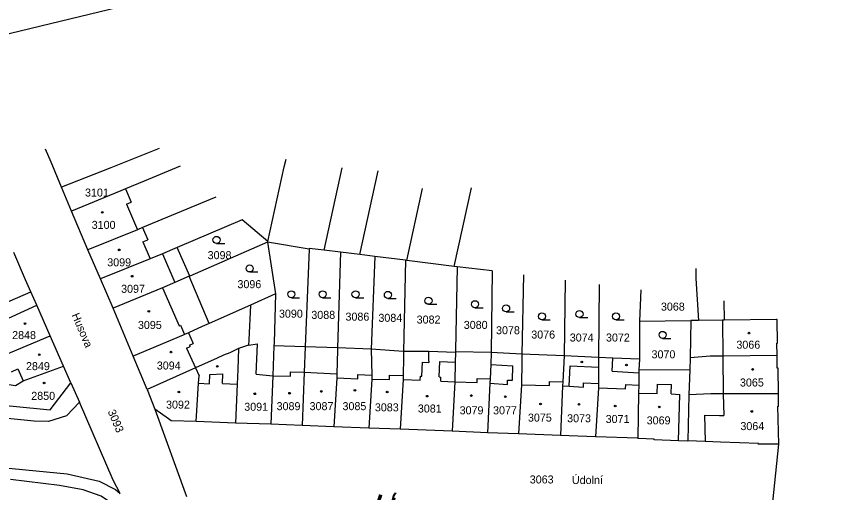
# Model space of a CAD drawing. Extents: x -738085 to -734306, y -1122197 to -1119753.
# Drawn here: x -734745.8 to -734573.1, y -1120143.5 to -1120042.4 of the extents above; entities that cross this region are included whole.
import ezdxf

# ---------------------------------------------------------------- set-up
doc = ezdxf.new("R2010")
doc.units = 0
for name, color, linetype in [('Hranice parcel', 7, 'Continuous'), ('Parcelní čísla', 7, 'Continuous'), ('Pop  PČ popisy', 7, 'Continuous'), ('Vnitřní kresba', 7, 'Continuous'), ('Vrstva 1', 7, 'Continuous'), ('Vrstva 7', 7, 'Continuous'), ('Značky budov', 7, 'Continuous'), ('Značky kultur', 7, 'Continuous')]:
    doc.layers.add(name, color=color, linetype=linetype)

msp = doc.modelspace()

# ---------------------------------------------------------------- linework, layer by layer
at = {"layer": 'Hranice parcel'}
for p, q in [((-734680.42, -1120092.08), (-734676.55, -1120074.57)), ((-734672.81, -1120093.01), (-734668.96, -1120075.25)), ((-734734, -1120083.8), (-734736.13, -1120078.7)), ((-734662.86, -1120094.24), (-734659.5, -1120078.96)), ((-734652.78, -1120095.52), (-734649.12, -1120078.87)), ((-734730.53, -1120091.97), (-734734, -1120083.8)), ((-734697.79, -1120085.62), (-734711.61, -1120091.5)), ((-734692.37, -1120090.23), (-734697.79, -1120085.62)), ((-734692.41, -1120090.4), (-734708.91, -1120097.56)), ((-734692.41, -1120090.4), (-734692.37, -1120090.23)), ((-734683.6, -1120091.87), (-734692.41, -1120090.4)), ((-734692.41, -1120090.4), (-734690.71, -1120101.34)), ((-734727.88, -1120098.19), (-734730.53, -1120091.97)), ((-734708.91, -1120097.56), (-734711.61, -1120091.5)), ((-734683.6, -1120091.87), (-734684.42, -1120112.56)), ((-734676.96, -1120092.51), (-734680.42, -1120092.08)), ((-734676.96, -1120092.51), (-734677.59, -1120112.79)), ((-734672.81, -1120093.01), (-734676.96, -1120092.51)), ((-734669.67, -1120093.4), (-734672.81, -1120093.01)), ((-734669.67, -1120093.4), (-734670.4, -1120113.05)), ((-734663.11, -1120094.23), (-734669.67, -1120093.4)), ((-734663.11, -1120094.23), (-734663.52, -1120113.54)), ((-734662.86, -1120094.24), (-734663.11, -1120094.23)), ((-734652.78, -1120095.52), (-734662.86, -1120094.24)), ((-734652.19, -1120095.59), (-734652.78, -1120095.52)), ((-734644.76, -1120096.47), (-734652.19, -1120095.59)), ((-734708.91, -1120097.56), (-734709.02, -1120097.6)), ((-734704.79, -1120107.63), (-734709.02, -1120097.6)), ((-734644.76, -1120096.47), (-734644.93, -1120113.82)), ((-734638.11, -1120097.31), (-734638.44, -1120114.16)), ((-734725.22, -1120104.37), (-734727.88, -1120098.19)), ((-734629.26, -1120098.44), (-734629.48, -1120114.51)), ((-734621.99, -1120099.36), (-734622.13, -1120114.88)), ((-734690.71, -1120101.34), (-734696.03, -1120103.72)), ((-734613.2, -1120100.48), (-734613.47, -1120107.14)), ((-734738.55, -1120110.28), (-734741.41, -1120103.73)), ((-734720.97, -1120114.53), (-734725.22, -1120104.37)), ((-734696.03, -1120103.72), (-734704.79, -1120107.63)), ((-734613.47, -1120107.14), (-734602.57, -1120106.99)), ((-734613.47, -1120107.14), (-734613.47, -1120115.18)), ((-734602.57, -1120106.99), (-734602.67, -1120114.92)), ((-734600.93, -1120106.97), (-734602.57, -1120106.99)), ((-734735.7, -1120116.71), (-734738.55, -1120110.28)), ((-734684.42, -1120112.56), (-734691.06, -1120112.35)), ((-734677.59, -1120112.79), (-734684.42, -1120112.56)), ((-734670.4, -1120113.05), (-734677.59, -1120112.79)), ((-734663.52, -1120113.54), (-734670.4, -1120113.05)), ((-734717.99, -1120121.62), (-734720.97, -1120114.53)), ((-734644.93, -1120113.82), (-734652.54, -1120113.64)), ((-734652.54, -1120113.64), (-734652.54, -1120113.79)), ((-734638.44, -1120114.16), (-734644.93, -1120113.82)), ((-734629.48, -1120114.51), (-734638.44, -1120114.16)), ((-734622.13, -1120114.88), (-734629.48, -1120114.51)), ((-734613.47, -1120115.18), (-734613.62, -1120117.52)), ((-734602.67, -1120114.92), (-734602.78, -1120117.44)), ((-734734.16, -1120120.2), (-734735.7, -1120116.71)), ((-734602.78, -1120117.44), (-734613.62, -1120117.52)), ((-734602.78, -1120117.44), (-734603.01, -1120122.78)), ((-734734.16, -1120120.2), (-734732.31, -1120124.29)), ((-734717.99, -1120121.62), (-734716.35, -1120125.79)), ((-734603.01, -1120122.78), (-734603.19, -1120132.52)), ((-734716.35, -1120125.79), (-734709.6, -1120144.34)), ((-734691.73, -1120129.02), (-734699.23, -1120128.75)), ((-734685.05, -1120129.27), (-734691.73, -1120129.02)), ((-734678.37, -1120129.56), (-734685.05, -1120129.27)), ((-734670.88, -1120129.86), (-734678.37, -1120129.56)), ((-734664.23, -1120130.05), (-734670.88, -1120129.86)), ((-734653.23, -1120130.5), (-734664.23, -1120130.05)), ((-734645.73, -1120130.82), (-734653.23, -1120130.5)), ((-734639.14, -1120131.04), (-734645.73, -1120130.82)), ((-734630.24, -1120131.41), (-734639.14, -1120131.04)), ((-734622.77, -1120131.68), (-734630.24, -1120131.41)), ((-734613.81, -1120131.98), (-734622.77, -1120131.68)), ((-734585.56, -1120149.21), (-734583.88, -1120133.2))]:
    msp.add_line(p, q, dxfattribs=at)
for points in [[(-734736.13, -1120078.7), (-734738.38, -1120073.38), (-734739.58, -1120070.62)], [(-734715.39, -1120070.51), (-734725.68, -1120074.58), (-734736.13, -1120078.7)], [(-734692.37, -1120090.23), (-734688.87, -1120074.42), (-734688.46, -1120072.79)], [(-734710.98, -1120074.27), (-734718.6, -1120077.41), (-734722.56, -1120079.04), (-734723.58, -1120079.46), (-734734, -1120083.8)], [(-734703.41, -1120080.84), (-734718.98, -1120087.3), (-734720.01, -1120087.73), (-734730.53, -1120091.97)], [(-734741.41, -1120103.73), (-734742.65, -1120100.94), (-734743.81, -1120098.34), (-734746.27, -1120092.6)], [(-734711.61, -1120091.5), (-734714.71, -1120092.82), (-734717.33, -1120093.93), (-734727.88, -1120098.19)], [(-734680.42, -1120092.08), (-734683.59, -1120091.7), (-734683.6, -1120091.87)], [(-734652.19, -1120095.59), (-734652.53, -1120113.36), (-734652.54, -1120113.64)], [(-734601.52, -1120095.93), (-734601.53, -1120098.07), (-734600.93, -1120106.97)], [(-734709.02, -1120097.6), (-734712.13, -1120098.95), (-734714.69, -1120100.06), (-734725.22, -1120104.37)], [(-734690.71, -1120101.34), (-734691.04, -1120111.73), (-734691.06, -1120112.35)], [(-734732.31, -1120124.29), (-734735.07, -1120127.22), (-734738.9, -1120128.4), (-734741.96, -1120128.37), (-734978.31, -1120104.89), (-734995.05, -1120103.5), (-735001.08, -1120103.64), (-735005.96, -1120104.65), (-735026.65, -1120111.99), (-735048.37, -1120119.26), (-735164.14, -1120157.32), (-735176.88, -1120160.91), (-735184.81, -1120162.43), (-735185.96, -1120162.53), (-735190.85, -1120162.98), (-735196.87, -1120162.75), (-735201.79, -1120161.48), (-735203.71, -1120160.98), (-735206.41, -1120159.5), (-735208.64, -1120157.56), (-735225.14, -1120141.26)], [(-734753.79, -1120107.64), (-734751.4, -1120108.03), (-734751.46, -1120107.88), (-734749.29, -1120107.32), (-734741.41, -1120103.73)], [(-734696.03, -1120103.72), (-734696.4, -1120111.12), (-734696.45, -1120112.2), (-734698.55, -1120112.94)], [(-734704.79, -1120107.63), (-734706.3, -1120108.3), (-734709.2, -1120109.6), (-734710.03, -1120109.96), (-734710.35, -1120110.11), (-734720.97, -1120114.53)], [(-734584.4, -1120106.77), (-734595.5, -1120106.9), (-734595.81, -1120106.9), (-734600.93, -1120106.97)], [(-734584.26, -1120114.44), (-734584.32, -1120111.82), (-734584.17, -1120111.82), (-734584.26, -1120106.77), (-734584.4, -1120106.77)], [(-735187.2, -1120177.07), (-735186.92, -1120175.94), (-735186.47, -1120174.12), (-735185.21, -1120172.48), (-735182.42, -1120171.13), (-735165.98, -1120166.38), (-735013.95, -1120116.34), (-735003.48, -1120113.01), (-735000.64, -1120112.19), (-735000, -1120112.13), (-734996.62, -1120111.83), (-734988.63, -1120112.11), (-734951.68, -1120115.51), (-734795.1, -1120131), (-734756.12, -1120134.99), (-734754.2, -1120137.32), (-734753.31, -1120137.78), (-734734.93, -1120139.52), (-734728.17, -1120141.08), (-734724.68, -1120142.84), (-734723.73, -1120143.69)], [(-734754.25, -1120116.86), (-734748.32, -1120114.37), (-734738.55, -1120110.28)], [(-734698.55, -1120112.94), (-734700.44, -1120113.83), (-734701.75, -1120114.37), (-734703.08, -1120115.02), (-734707.73, -1120117.04), (-734717.99, -1120121.62)], [(-734698.55, -1120112.94), (-734698.74, -1120117.36), (-734698.88, -1120120.5), (-734699.23, -1120128.75)], [(-734691.06, -1120112.35), (-734691.32, -1120118.72), (-734691.73, -1120129.02)], [(-734684.42, -1120112.56), (-734684.64, -1120117.95), (-734685.05, -1120129.27)], [(-734677.59, -1120112.79), (-734677.6, -1120113.26), (-734677.72, -1120118.31), (-734677.74, -1120119.17), (-734678.37, -1120129.56)], [(-734670.4, -1120113.05), (-734670.28, -1120118.59), (-734670.26, -1120119.45), (-734670.88, -1120129.86)], [(-734663.52, -1120113.54), (-734663.55, -1120114.85), (-734663.62, -1120118.67), (-734663.63, -1120119.54), (-734664.23, -1120130.05)], [(-734652.54, -1120113.79), (-734658.19, -1120113.59), (-734663.52, -1120113.54)], [(-734652.54, -1120113.79), (-734652.58, -1120115.81), (-734652.66, -1120119.99), (-734653.23, -1120130.5)], [(-734644.93, -1120113.82), (-734645.05, -1120116.35), (-734645.19, -1120119.36), (-734645.23, -1120120.26), (-734645.73, -1120130.82)], [(-734638.44, -1120114.16), (-734638.47, -1120116.66), (-734638.51, -1120119.71), (-734638.52, -1120120.65), (-734639.14, -1120131.04)], [(-734629.48, -1120114.51), (-734629.73, -1120120.02), (-734629.77, -1120120.88), (-734630.24, -1120131.41)], [(-734622.13, -1120114.88), (-734622.15, -1120116.92), (-734622.18, -1120120.36), (-734622.19, -1120121.25), (-734622.77, -1120131.68)], [(-734613.47, -1120115.18), (-734619.14, -1120114.98), (-734622.13, -1120114.88)], [(-734584.26, -1120114.44), (-734595.79, -1120114.55), (-734598.45, -1120114.58), (-734602.67, -1120114.92)], [(-734583.98, -1120122.55), (-734584.05, -1120117.09), (-734584.2, -1120117.09), (-734584.26, -1120114.44)], [(-734754.43, -1120119.69), (-734747.32, -1120120.59), (-734745.89, -1120120.77), (-734744.27, -1120119.8), (-734735.7, -1120116.71)], [(-734613.62, -1120117.52), (-734613.63, -1120118.11), (-734613.61, -1120120.72), (-734613.69, -1120122.41), (-734613.81, -1120131.98)], [(-734754.69, -1120124.4), (-734746.39, -1120125.14), (-734738.56, -1120125.97), (-734734.16, -1120120.2)], [(-734583.98, -1120122.55), (-734595.67, -1120122.56), (-734598.31, -1120122.56), (-734603.01, -1120122.78)], [(-734583.88, -1120133.2), (-734584.08, -1120125.19), (-734583.94, -1120125.19), (-734583.98, -1120122.55)], [(-734723.73, -1120143.69), (-734725.18, -1120140.86), (-734732.31, -1120124.29)], [(-734699.23, -1120128.75), (-734707.54, -1120128.46), (-734712.88, -1120128.26), (-734713.42, -1120127.87), (-734716.35, -1120125.79)], [(-734603.19, -1120132.52), (-734603.19, -1120132.58), (-734605.18, -1120132.53), (-734610.37, -1120132.29), (-734610.36, -1120132.14), (-734613.76, -1120132.06), (-734613.81, -1120131.98)], [(-734583.88, -1120133.2), (-734584.36, -1120133.25), (-734588.24, -1120133.27), (-734588.23, -1120133.07), (-734596.23, -1120132.78), (-734599.51, -1120132.66), (-734603.19, -1120132.52)], [(-734719.95, -1120151.88), (-734721.91, -1120149.18), (-734724.49, -1120146.43), (-734727.73, -1120144.25), (-734731.57, -1120142.94), (-734736.55, -1120141.99), (-734746.98, -1120140.71)]]:
    msp.add_lwpolyline(points, dxfattribs=at)
at = {"layer": 'Vnitřní kresba'}
for p, q in [((-734722.56, -1120079.04), (-734721.33, -1120081.9)), ((-734722.34, -1120082.33), (-734721.33, -1120081.9)), ((-734722.34, -1120082.33), (-734720.01, -1120087.73)), ((-734718.98, -1120087.3), (-734717.86, -1120089.88)), ((-734718.89, -1120090.33), (-734717.86, -1120089.88)), ((-734718.89, -1120090.33), (-734717.33, -1120093.93)), ((-734714.71, -1120092.82), (-734712.13, -1120098.95)), ((-734748.71, -1120103.56), (-734742.65, -1120100.94)), ((-734714.69, -1120100.06), (-734711.19, -1120108.15)), ((-734595.56, -1120102.82), (-734595.5, -1120106.9)), ((-734711.19, -1120108.15), (-734710.87, -1120108.02)), ((-734710.87, -1120108.02), (-734710.03, -1120109.96)), ((-734595.81, -1120106.9), (-734595.79, -1120114.55)), ((-734709.2, -1120109.6), (-734708.18, -1120111.9)), ((-734709.63, -1120112.89), (-734708.85, -1120112.53)), ((-734709.63, -1120112.89), (-734707.73, -1120117.04)), ((-734708.97, -1120112.26), (-734708.18, -1120111.9)), ((-734708.97, -1120112.26), (-734708.85, -1120112.53)), ((-734696.45, -1120112.2), (-734694.58, -1120111.93)), ((-734694.83, -1120118.38), (-734694.58, -1120111.93)), ((-734658.2, -1120115.61), (-734658.19, -1120113.59)), ((-734619.24, -1120117.75), (-734619.14, -1120114.98)), ((-734595.79, -1120114.55), (-734595.67, -1120122.56)), ((-734707.73, -1120117.04), (-734706.95, -1120118.75)), ((-734659.65, -1120118.82), (-734659.53, -1120115.84)), ((-734659.53, -1120115.84), (-734658.19, -1120115.89)), ((-734658.2, -1120115.61), (-734658.19, -1120115.89)), ((-734655.97, -1120118.98), (-734655.81, -1120115.7)), ((-734655.81, -1120115.7), (-734652.58, -1120115.81)), ((-734645.05, -1120116.35), (-734640.38, -1120116.63)), ((-734640.42, -1120119.69), (-734640.38, -1120116.63)), ((-734628.42, -1120120.95), (-734628.19, -1120116.63)), ((-734628.19, -1120116.63), (-734622.15, -1120116.92)), ((-734746.8, -1120117.88), (-734745.41, -1120117.28)), ((-734745.41, -1120117.28), (-734744.27, -1120119.8)), ((-734707.04, -1120120.3), (-734706.95, -1120118.75)), ((-734704.76, -1120120.44), (-734704.64, -1120118.47)), ((-734704.64, -1120118.47), (-734701.88, -1120118.32)), ((-734701.95, -1120120.37), (-734701.88, -1120118.32)), ((-734694.83, -1120118.38), (-734691.32, -1120118.72)), ((-734691.32, -1120118.72), (-734687.56, -1120118.78)), ((-734687.56, -1120118.78), (-734687.55, -1120117.9)), ((-734687.55, -1120117.9), (-734684.64, -1120117.95)), ((-734684.64, -1120117.95), (-734677.72, -1120118.31)), ((-734673.27, -1120119.36), (-734673.23, -1120118.47)), ((-734673.23, -1120118.47), (-734670.28, -1120118.59)), ((-734666.55, -1120119.51), (-734666.53, -1120118.62)), ((-734666.53, -1120118.62), (-734663.62, -1120118.67)), ((-734619.24, -1120117.75), (-734613.63, -1120118.11)), ((-734707.54, -1120128.46), (-734707.04, -1120120.3)), ((-734707.04, -1120120.3), (-734704.76, -1120120.44)), ((-734701.95, -1120120.37), (-734698.88, -1120120.5)), ((-734677.74, -1120119.17), (-734673.27, -1120119.36)), ((-734670.26, -1120119.45), (-734666.55, -1120119.51)), ((-734663.63, -1120119.54), (-734660.01, -1120119.69)), ((-734660.01, -1120119.69), (-734659.97, -1120118.81)), ((-734659.97, -1120118.81), (-734659.65, -1120118.82)), ((-734655.97, -1120118.98), (-734655.63, -1120119)), ((-734655.66, -1120119.87), (-734655.63, -1120119)), ((-734655.66, -1120119.87), (-734652.66, -1120119.99)), ((-734652.66, -1120119.99), (-734647.93, -1120120.15)), ((-734647.93, -1120120.15), (-734647.9, -1120119.27)), ((-734647.9, -1120119.27), (-734645.19, -1120119.36)), ((-734645.23, -1120120.26), (-734641.5, -1120120.61)), ((-734641.5, -1120120.61), (-734641.49, -1120119.68)), ((-734641.49, -1120119.68), (-734640.42, -1120119.69)), ((-734632.58, -1120120.82), (-734632.55, -1120119.94)), ((-734632.55, -1120119.94), (-734629.73, -1120120.02)), ((-734625.35, -1120121.11), (-734625.31, -1120120.2)), ((-734625.31, -1120120.2), (-734622.18, -1120120.36)), ((-734609.71, -1120122.5), (-734609.65, -1120120.51)), ((-734609.65, -1120120.51), (-734606.67, -1120120.6)), ((-734638.52, -1120120.65), (-734632.58, -1120120.82)), ((-734629.77, -1120120.88), (-734628.42, -1120120.95)), ((-734628.42, -1120120.95), (-734625.35, -1120121.11)), ((-734622.19, -1120121.25), (-734616.41, -1120121.5)), ((-734616.41, -1120121.5), (-734616.37, -1120120.6)), ((-734616.37, -1120120.6), (-734613.61, -1120120.72)), ((-734606.73, -1120122.58), (-734606.67, -1120120.6)), ((-734613.69, -1120122.41), (-734609.71, -1120122.5)), ((-734606.73, -1120122.58), (-734604.91, -1120122.7)), ((-734605.18, -1120132.53), (-734604.91, -1120122.7)), ((-734595.67, -1120122.56), (-734595.54, -1120127.12)), ((-734599.64, -1120127.11), (-734596.46, -1120127.16)), ((-734599.64, -1120127.11), (-734599.51, -1120132.66)), ((-734596.46, -1120127.16), (-734595.54, -1120127.12))]:
    msp.add_line(p, q, dxfattribs=at)
at = {"layer": 'Vrstva 1'}
msp.add_lwpolyline([(-734541.63, -1119996.45), (-735348.44, -1120191.3), (-735283.42, -1120460.56), (-734476.61, -1120265.71)], close=True, dxfattribs=at)
at = {"layer": 'Značky budov'}
for centre in [(-734727.49, -1120084.06), (-734723.9, -1120092.02), (-734721.16, -1120097.6), (-734717.63, -1120105.05), (-734743.9, -1120107.65), (-734590.23, -1120109.67), (-734712.9, -1120113.7), (-734740.86, -1120114.25), (-734703.09, -1120116.73), (-734625.7, -1120115.79), (-734616.23, -1120116.45), (-734589.45, -1120117.38), (-734739.84, -1120120.24), (-734711.23, -1120122.17), (-734687.75, -1120122.42), (-734681, -1120122.05), (-734673.88, -1120121.8), (-734667.01, -1120122.17), (-734695.12, -1120122.55), (-734658.52, -1120123.05), (-734649.15, -1120122.92), (-734641.94, -1120123.16), (-734634.47, -1120124.71), (-734626.29, -1120124.78), (-734618.61, -1120125.14), (-734609.26, -1120125.34), (-734589.62, -1120126.29)]:
    msp.add_circle(centre, 0.175, dxfattribs=at)
at = {"layer": 'Značky kultur'}
for p, q in [((-734703.25, -1120090.64), (-734701.5, -1120090.64)), ((-734696.21, -1120096.7), (-734694.46, -1120096.7)), ((-734687.35, -1120102.18), (-734685.6, -1120102.18)), ((-734680.73, -1120102.18), (-734678.98, -1120102.18)), ((-734673.74, -1120102.18), (-734671.99, -1120102.18)), ((-734666.87, -1120102.31), (-734665.12, -1120102.31)), ((-734658.25, -1120103.56), (-734656.5, -1120103.56)), ((-734648.38, -1120104.3), (-734646.63, -1120104.3)), ((-734641.78, -1120105.18), (-734640.03, -1120105.18)), ((-734626.2, -1120106.38), (-734624.45, -1120106.38)), ((-734634.17, -1120106.87), (-734632.42, -1120106.87)), ((-734618.45, -1120106.87), (-734616.7, -1120106.87)), ((-734608.55, -1120110.8), (-734606.8, -1120110.8))]:
    msp.add_line(p, q, dxfattribs=at)
for centre in [(-734703.25, -1120089.89), (-734696.21, -1120095.95), (-734687.35, -1120101.43), (-734680.73, -1120101.43), (-734673.74, -1120101.43), (-734666.87, -1120101.56), (-734658.25, -1120102.81), (-734648.38, -1120103.55), (-734641.78, -1120104.43), (-734626.2, -1120105.63), (-734634.17, -1120106.12), (-734618.45, -1120106.12), (-734608.55, -1120110.05)]:
    msp.add_circle(centre, 0.75, dxfattribs=at)

# ---------------------------------------------------------------- texts
at = {"layer": 'Parcelní čísla'}
for s, p in [('3101', (-734731.16, -1120080.7)), ('3100', (-734729.74, -1120087.56)), ('3098', (-734705.13, -1120093.98)), ('3099', (-734726.44, -1120095.5)), ('3097', (-734723.5, -1120101.12)), ('3096', (-734698.8, -1120100.14)), ('3068', (-734608.91, -1120104.9)), ('3090', (-734689.99, -1120106.4)), ('3088', (-734683.12, -1120106.65)), ('3086', (-734675.87, -1120107.03)), ('3084', (-734668.88, -1120107.28)), ('3082', (-734660.76, -1120107.65)), ('3095', (-734719.93, -1120108.79)), ('3080', (-734650.76, -1120108.78)), ('3078', (-734643.91, -1120109.91)), ('2848', (-734746.63, -1120110.94)), ('3076', (-734636.43, -1120110.83)), ('3074', (-734628.26, -1120111.46)), ('3072', (-734620.57, -1120111.46)), ('3066', (-734592.89, -1120112.98)), ('3070', (-734610.9, -1120115.02)), ('2849', (-734743.69, -1120117.53)), ('3094', (-734715.92, -1120117.4)), ('3065', (-734592.13, -1120121)), ('2850', (-734742.57, -1120123.83)), ('3092', (-734713.96, -1120125.7)), ('3091', (-734697.36, -1120126.15)), ('3089', (-734690.49, -1120126.02)), ('3087', (-734683.49, -1120126.02)), ('3085', (-734676.5, -1120126.02)), ('3083', (-734669.63, -1120126.27)), ('3081', (-734660.51, -1120126.52)), ('3079', (-734651.64, -1120126.9)), ('3077', (-734644.54, -1120126.9)), ('3075', (-734637.14, -1120128.45)), ('3073', (-734628.82, -1120128.59)), ('3071', (-734620.64, -1120128.74)), ('3069', (-734611.93, -1120129.04)), ('3064', (-734592.04, -1120130.25)), ('3063', (-734636.75, -1120141.57))]:
    msp.add_text(s, height=1.7, dxfattribs=at).set_placement(p)
msp.add_text('3093', height=1.7, rotation=293, dxfattribs=at).set_placement((-734726.38, -1120126.31))
at = {"layer": 'Pop  PČ popisy'}
msp.add_text('Husova', height=1.7, rotation=293, dxfattribs=at).set_placement((-734734.03, -1120105.84))
msp.add_text('Údolní', height=1.7, dxfattribs=at).set_placement((-734627.8, -1120141.69))
at = {"layer": 'Vrstva 7'}
msp.add_text('0,7', height=6, rotation=167.2383, dxfattribs=at).set_placement((-734660.13, -1120145.82))

doc.saveas('drawing.dxf')
